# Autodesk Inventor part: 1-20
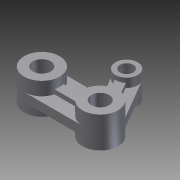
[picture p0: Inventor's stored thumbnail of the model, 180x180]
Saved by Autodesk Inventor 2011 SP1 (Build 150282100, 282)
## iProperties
Created: 2014-02
Part Number: 1-20
Document SubType Name: Modeling
Designer: Administrator
Density: 1 g/cm^3
Author: Administrator
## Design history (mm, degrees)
sketch "草图1"
  geometry: L1 (-26.261, 8)-(-10.471, 8); L2 (-26.261, -8)-(0, -8); L3 (-4.006, 22.727)-(6.909, 4.034); L4 (-12.641, 17.685)-(-8.743, 11.008); A1 r 8 centre (0, 0) between (0, -8) and (6.909, 4.034); A2 r 8 centre (-26.261, 0) between (-26.261, 8) and (-26.261, -8); A3 r 5 centre (-8.324, 20.206) between (-4.006, 22.727) and (-12.641, 17.685); A4 r 2 centre (-10.471, 10) between (-10.471, 8) and (-8.743, 11.008); 1 further point
  constraints: 8 end point, 8 point on circle, 8 tangent, 4 centre point, 1 coincident
  dimensions: "d0" = 16 diameter of A1; "d1" = 16 diameter of A2; "d2" = 10 diameter of A3; "d3" = 2 radius of A4
extrude "拉伸1" new body sketch "草图1" distance "d4" = 4; taper "d5" = 0 deg
sketch "草图3"
  geometry: A1 r 8 centre (26.261, 0) between (26.261, -8) and (26.261, 8) reference; A2 r 8 centre (0, 0) between (-6.909, 4.034) and (0, -8) reference; 2 further points
  constraints: 2 coincident, 2 vertical alignment, 4 other
extrude "拉伸3" join sketch "草图3" distance "d8" = 4; taper "d9" = 0 deg
sketch "草图4"
  geometry: C1 r 5 at (8.324, 20.206); A1 r 5 centre (8.324, 20.206) between (12.641, 17.685) and (4.006, 22.727) reference
  constraints: 1 centre point, 1 coincident, 1 concentric
extrude "拉伸4" join sketch "草图4" distance "d10" = 4; taper "d11" = 0 deg
sketch "草图5"
  geometry: C1 r 8 at (0, 0); C2 r 8 at (-26.261, 0); A1 r 8 centre (-26.261, 0) between (-26.261, 8) and (-26.261, -8) reference; A2 r 8 centre (0, 0) between (0, -8) and (6.909, 4.034) reference
  constraints: 2 centre point, 2 coincident, 2 concentric
extrude "拉伸5" join sketch "草图5" distance "d12" = 6; taper "d13" = 0 deg
sketch "草图6"
  geometry: C1 r 5 at (-8.324, 20.206); A1 r 5 centre (-8.324, 20.206) between (-4.006, 22.727) and (-12.641, 17.685) reference
  constraints: 1 centre point, 1 coincident, 1 concentric
extrude "拉伸6" join sketch "草图6" distance "d14" = 4; taper "d15" = 0 deg
sketch "草图7"
  geometry: L1 (0, -8)-(-26.261, -8) reference; L2 (-4.006, 22.727)-(6.909, 4.034) reference; L3 (-7.74, 2.024)-(-18.522, 2.024); L4 (-7.727, -2.071)-(-18.534, -2.071); L5 (-0.068, 8)-(-5.009, 16.462); L6 (-8.736, 15.223)-(-3.845, 7.015); A1 r 5 centre (-8.324, 20.206) between (-12.641, 17.685) and (-4.006, 22.727) reference; A2 r 8 centre (-26.261, 0) between (-26.261, -8) and (-26.261, 8) reference; A3 r 8 centre (0, 0) between (6.909, 4.034) and (0, -8) reference; A4 r 8 centre (0, 0) between (0, -8) and (6.909, 4.034) reference
  constraints: 12 point on circle, 8 end point, 3 parallel
extrude "拉伸7" join sketch "草图7" distance "d16" = 2; taper "d17" = 0 deg
sketch "草图8"
  geometry: L1 (7.727, -2.071)-(18.534, -2.071) reference; L2 (18.522, 2.024)-(7.74, 2.024) reference; L3 (3.845, 7.015)-(8.736, 15.223) reference; L4 (5.009, 16.462)-(0.068, 8) reference; A1 r 8 centre (0, 0) between (7.727, -2.071) and (7.74, 2.024) reference; A2 r 5 centre (8.324, 20.206) between (8.736, 15.223) and (5.009, 16.462) reference; A3 r 8 centre (26.261, 0) between (18.534, -2.071) and (18.522, 2.024) reference
extrude "拉伸8" join sketch "草图8" distance "d18" = 2; taper "d19" = 0 deg
hole "Hole1" diameter "d22" = 8; stored, may be unused: countersink angle "d26" = 90 deg, drill point angle "d28" = 0 deg; dims "d20" = 10, "d21" = 10, "d23" = 6, "d24" = 4, "d25" = 2, "d27" = 8
hole "Hole2" diameter "d31" = 8; stored, may be unused: countersink angle "d35" = 90 deg, drill point angle "d37" = 0 deg; dims "d29" = 10, "d30" = 10, "d32" = 6, "d33" = 4, "d34" = 2, "d36" = 8
hole "Hole3" diameter "d40" = 6; stored, may be unused: countersink angle "d44" = 90 deg, drill point angle "d46" = 118 deg; dims "d38" = 10, "d39" = 10, "d41" = 6, "d42" = 4, "d43" = 2, "d45" = 8
node "实体1"
